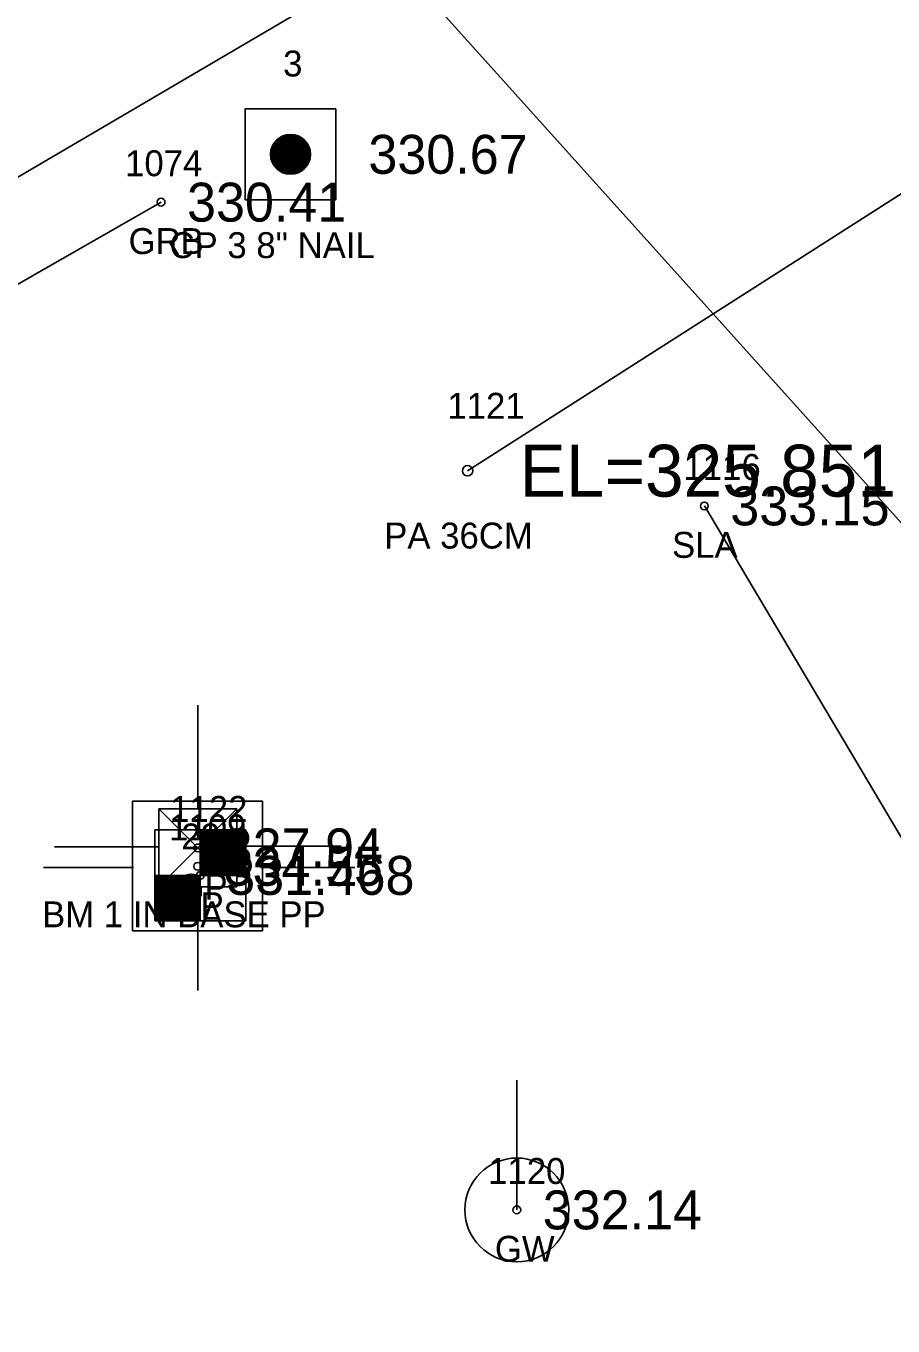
# Model space of a CAD drawing. Extents: x 2231119 to 2232595, y 1035731 to 1037094.
# Drawn here: x 2231678 to 2231711.4, y 1036450.5 to 1036500.6 of the extents above; entities that cross this region are included whole.
import ezdxf

# ---------------------------------------------------------------- set-up
doc = ezdxf.new("R2010")
doc.units = 0
for name, color, linetype in [('RD_EX_DR_Pipe', 7, 'Continuous'), ('RD_EX_DR_Pipe_txCode', 7, 'Continuous'), ('RD_EX_Driveway', 7, 'Continuous'), ('RD_EX_GuardRail', 7, 'Continuous'), ('RD_EX_GuardRail_txCode', 7, 'Continuous'), ('RD_EX_Road', 7, 'Continuous'), ('RD_EX_TX_GuardRail_ELEV', 7, 'Continuous'), ('RD_EX_TX_UT_ELEV', 7, 'Continuous'), ('RD_EX_TX_VEG_ELEV', 7, 'Continuous'), ('RD_EX_UT', 7, 'Continuous'), ('RD_EX_UT_txCode', 7, 'Continuous'), ('RD_EX_VEG', 7, 'Continuous'), ('RD_EX_VEG_txCode', 7, 'Continuous'), ('RD_HC_Survey', 7, 'Continuous'), ('RD_HC_Survey_ELEV', 7, 'Continuous'), ('RD_HC_Survey_txCode', 7, 'Continuous'), ('RD_SMD_Locator', 7, 'Continuous'), ('RD_TX_Pipe_ElevEX', 7, 'Continuous')]:
    doc.layers.add(name, color=color, linetype=linetype)

msp = doc.modelspace()

# ---------------------------------------------------------------- linework, layer by layer
at = {"layer": 'RD_EX_DR_Pipe'}
msp.add_line((2231694.987, 1036483.445), (2231720.193, 1036499.548), dxfattribs=at)
at = {"layer": 'RD_EX_Driveway'}
msp.add_lwpolyline([(2231692.093, 1036503.238), (2231712.625, 1036480.399), (2231730.963, 1036467.852)], dxfattribs=at)
at = {"layer": 'RD_EX_GuardRail'}
msp.add_lwpolyline([(2231470.541, 1036358.212), (2231510.971, 1036390.403), (2231547.273, 1036414.453), (2231612.034, 1036453.053), (2231683.178, 1036493.793)], dxfattribs=at)
at = {"layer": 'RD_EX_Road'}
msp.add_lwpolyline([(2231606.098, 1036462.918), (2231610.57, 1036455.357), (2231692.093, 1036503.238), (2231706.071, 1036512.594), (2231777.095, 1036553.27), (2231861.393, 1036604.653), (2231946.389, 1036654.771), (2232031.075, 1036704.2), (2232117.063, 1036755.157), (2232199.91, 1036803.805), (2232286.695, 1036855.364)], dxfattribs=at)
at = {"layer": 'RD_EX_UT'}
for p, q in [((2231684.591, 1036470.408), (2231684.591, 1036474.408)), ((2231687.079, 1036470.709), (2231682.079, 1036470.709)), ((2231682.079, 1036470.709), (2231682.079, 1036465.709)), ((2231687.079, 1036465.709), (2231687.079, 1036470.709)), ((2231686.091, 1036470.408), (2231683.091, 1036467.408)), ((2231683.091, 1036470.408), (2231686.091, 1036467.408)), ((2231686.091, 1036470.408), (2231683.091, 1036470.408)), ((2231683.091, 1036470.408), (2231683.091, 1036467.408)), ((2231686.091, 1036467.408), (2231686.091, 1036470.408)), ((2231683.067, 1036468.956), (2231679.067, 1036468.956)), ((2231686.105, 1036468.974), (2231690.121, 1036468.974)), ((2231678.648, 1036468.147), (2231682.117, 1036468.147)), ((2231687.008, 1036468.147), (2231690.648, 1036468.147)), ((2231683.091, 1036467.408), (2231686.091, 1036467.408)), ((2231684.591, 1036467.408), (2231684.591, 1036463.408)), ((2231682.079, 1036465.709), (2231687.079, 1036465.709)), ((2231696.881, 1036454.958), (2231696.881, 1036459.958))]:
    msp.add_line(p, q, dxfattribs=at)
msp.add_circle((2231696.881, 1036454.958), 1.999, dxfattribs=at)
at = {"layer": 'RD_EX_VEG'}
msp.add_line((2231704.106, 1036482.087), (2231712.557, 1036467.849), dxfattribs=at)
at = {"layer": 'RD_HC_Survey'}
for p, q in [((2231687.688, 1036495.032), (2231687.688, 1036496.241)), ((2231687.713, 1036495.013), (2231687.713, 1036496.259)), ((2231687.737, 1036494.996), (2231687.737, 1036496.277)), ((2231687.762, 1036494.98), (2231687.762, 1036496.293)), ((2231687.787, 1036494.966), (2231687.787, 1036496.307)), ((2231687.812, 1036494.952), (2231687.812, 1036496.32)), ((2231687.836, 1036494.94), (2231687.836, 1036496.333)), ((2231687.861, 1036494.929), (2231687.861, 1036496.344)), ((2231687.886, 1036494.919), (2231687.886, 1036496.354)), ((2231687.911, 1036494.91), (2231687.911, 1036496.363)), ((2231687.935, 1036494.902), (2231687.935, 1036496.371)), ((2231687.96, 1036494.894), (2231687.96, 1036496.378)), ((2231687.985, 1036494.888), (2231687.985, 1036496.385)), ((2231688.01, 1036494.882), (2231688.01, 1036496.39)), ((2231688.034, 1036494.878), (2231688.034, 1036496.395)), ((2231688.059, 1036494.874), (2231688.059, 1036496.399)), ((2231688.084, 1036494.871), (2231688.084, 1036496.402)), ((2231688.109, 1036494.869), (2231688.109, 1036496.404)), ((2231688.133, 1036494.867), (2231688.133, 1036496.405)), ((2231688.158, 1036494.867), (2231688.158, 1036496.406)), ((2231688.183, 1036494.867), (2231688.183, 1036496.406)), ((2231688.208, 1036494.868), (2231688.208, 1036496.405)), ((2231688.232, 1036494.87), (2231688.232, 1036496.403)), ((2231688.257, 1036494.872), (2231688.257, 1036496.4)), ((2231688.282, 1036494.876), (2231688.282, 1036496.397)), ((2231688.307, 1036494.88), (2231688.307, 1036496.392)), ((2231688.331, 1036494.885), (2231688.331, 1036496.387)), ((2231688.356, 1036494.891), (2231688.356, 1036496.381)), ((2231688.381, 1036494.898), (2231688.381, 1036496.375)), ((2231688.406, 1036494.906), (2231688.406, 1036496.367)), ((2231688.43, 1036494.914), (2231688.43, 1036496.358)), ((2231688.455, 1036494.924), (2231688.455, 1036496.349)), ((2231688.48, 1036494.935), (2231688.48, 1036496.338)), ((2231688.505, 1036494.946), (2231688.505, 1036496.326)), ((2231688.529, 1036494.959), (2231688.529, 1036496.314)), ((2231688.554, 1036494.973), (2231688.554, 1036496.3)), ((2231688.579, 1036494.988), (2231688.579, 1036496.284)), ((2231688.604, 1036495.005), (2231688.604, 1036496.268)), ((2231688.628, 1036495.023), (2231688.628, 1036496.25)), ((2231687.416, 1036495.457), (2231687.416, 1036495.815)), ((2231687.44, 1036495.375), (2231687.44, 1036495.898)), ((2231687.465, 1036495.314), (2231687.465, 1036495.958)), ((2231687.49, 1036495.265), (2231687.49, 1036496.007)), ((2231687.515, 1036495.223), (2231687.515, 1036496.049)), ((2231687.539, 1036495.187), (2231687.539, 1036496.086)), ((2231687.564, 1036495.154), (2231687.564, 1036496.118)), ((2231687.589, 1036495.125), (2231687.589, 1036496.148)), ((2231687.614, 1036495.099), (2231687.614, 1036496.174)), ((2231687.638, 1036495.074), (2231687.638, 1036496.198)), ((2231687.663, 1036495.052), (2231687.663, 1036496.22)), ((2231688.653, 1036495.042), (2231688.653, 1036496.23)), ((2231688.678, 1036495.064), (2231688.678, 1036496.209)), ((2231688.703, 1036495.087), (2231688.703, 1036496.186)), ((2231688.727, 1036495.112), (2231688.727, 1036496.16)), ((2231688.752, 1036495.14), (2231688.752, 1036496.133)), ((2231688.777, 1036495.171), (2231688.777, 1036496.102)), ((2231688.802, 1036495.205), (2231688.802, 1036496.067)), ((2231688.826, 1036495.245), (2231688.826, 1036496.028)), ((2231688.851, 1036495.29), (2231688.851, 1036495.983)), ((2231688.876, 1036495.344), (2231688.876, 1036495.929)), ((2231688.901, 1036495.414), (2231688.901, 1036495.859)), ((2231688.925, 1036495.525), (2231688.925, 1036495.748)), ((2231684.689, 1036469.599), (2231684.689, 1036466.099)), ((2231684.706, 1036469.599), (2231684.706, 1036467.849)), ((2231684.731, 1036469.599), (2231684.731, 1036467.849)), ((2231684.756, 1036469.599), (2231684.756, 1036467.849)), ((2231684.78, 1036469.599), (2231684.78, 1036467.849)), ((2231684.805, 1036469.599), (2231684.805, 1036467.849)), ((2231684.83, 1036469.599), (2231684.83, 1036467.849)), ((2231684.855, 1036469.599), (2231684.855, 1036467.849)), ((2231684.879, 1036469.599), (2231684.879, 1036467.849)), ((2231684.904, 1036469.599), (2231684.904, 1036467.849)), ((2231684.929, 1036469.599), (2231684.929, 1036467.849)), ((2231684.954, 1036469.599), (2231684.954, 1036467.849)), ((2231684.978, 1036469.599), (2231684.978, 1036467.849)), ((2231685.003, 1036469.599), (2231685.003, 1036467.849)), ((2231685.028, 1036469.599), (2231685.028, 1036467.849)), ((2231685.053, 1036469.599), (2231685.053, 1036467.849)), ((2231685.077, 1036469.599), (2231685.077, 1036467.849)), ((2231685.102, 1036469.599), (2231685.102, 1036467.849)), ((2231685.127, 1036469.599), (2231685.127, 1036467.849)), ((2231685.152, 1036469.599), (2231685.152, 1036467.849)), ((2231685.176, 1036469.599), (2231685.176, 1036467.849)), ((2231685.201, 1036469.599), (2231685.201, 1036467.849)), ((2231685.226, 1036469.599), (2231685.226, 1036467.849)), ((2231685.251, 1036469.599), (2231685.251, 1036467.849)), ((2231685.275, 1036469.599), (2231685.275, 1036467.849)), ((2231685.3, 1036469.599), (2231685.3, 1036467.849)), ((2231685.325, 1036469.599), (2231685.325, 1036467.849)), ((2231685.35, 1036469.599), (2231685.35, 1036467.849)), ((2231685.374, 1036469.599), (2231685.374, 1036467.849)), ((2231685.399, 1036469.599), (2231685.399, 1036467.849)), ((2231685.424, 1036469.599), (2231685.424, 1036467.849)), ((2231685.449, 1036469.599), (2231685.449, 1036467.849)), ((2231685.473, 1036469.599), (2231685.473, 1036467.849)), ((2231685.498, 1036469.599), (2231685.498, 1036467.849)), ((2231685.523, 1036469.599), (2231685.523, 1036467.849)), ((2231685.548, 1036469.599), (2231685.548, 1036467.849)), ((2231685.572, 1036469.599), (2231685.572, 1036467.849)), ((2231685.597, 1036469.599), (2231685.597, 1036467.849)), ((2231685.622, 1036469.599), (2231685.622, 1036467.849)), ((2231685.647, 1036469.599), (2231685.647, 1036467.849)), ((2231685.671, 1036469.599), (2231685.671, 1036467.849)), ((2231685.696, 1036469.599), (2231685.696, 1036467.849)), ((2231685.721, 1036469.599), (2231685.721, 1036467.849)), ((2231685.746, 1036469.599), (2231685.746, 1036467.849)), ((2231685.77, 1036469.599), (2231685.77, 1036467.849)), ((2231685.795, 1036469.599), (2231685.795, 1036467.849)), ((2231685.82, 1036469.599), (2231685.82, 1036467.849)), ((2231685.845, 1036469.599), (2231685.845, 1036467.849)), ((2231685.869, 1036469.599), (2231685.869, 1036467.849)), ((2231685.894, 1036469.599), (2231685.894, 1036467.849)), ((2231685.919, 1036469.599), (2231685.919, 1036467.849)), ((2231685.944, 1036469.599), (2231685.944, 1036467.849)), ((2231685.968, 1036469.599), (2231685.968, 1036467.849)), ((2231685.993, 1036469.599), (2231685.993, 1036467.849)), ((2231686.018, 1036469.599), (2231686.018, 1036467.849)), ((2231686.043, 1036469.599), (2231686.043, 1036467.849)), ((2231686.067, 1036469.599), (2231686.067, 1036467.849)), ((2231686.092, 1036469.599), (2231686.092, 1036467.849)), ((2231686.117, 1036469.599), (2231686.117, 1036467.849)), ((2231686.142, 1036469.599), (2231686.142, 1036467.849)), ((2231686.166, 1036469.599), (2231686.166, 1036467.849)), ((2231686.191, 1036469.599), (2231686.191, 1036467.849)), ((2231686.216, 1036469.599), (2231686.216, 1036467.849)), ((2231686.241, 1036469.599), (2231686.241, 1036467.849)), ((2231686.265, 1036469.599), (2231686.265, 1036467.849)), ((2231686.29, 1036469.599), (2231686.29, 1036467.849)), ((2231686.315, 1036469.599), (2231686.315, 1036467.849)), ((2231686.34, 1036469.599), (2231686.34, 1036467.849)), ((2231686.364, 1036469.599), (2231686.364, 1036467.849)), ((2231686.389, 1036469.599), (2231686.389, 1036467.849)), ((2231686.414, 1036469.599), (2231686.414, 1036467.849)), ((2231686.439, 1036467.849), (2231682.939, 1036467.849)), ((2231682.939, 1036467.849), (2231682.939, 1036466.099)), ((2231682.963, 1036467.849), (2231682.963, 1036466.099)), ((2231682.988, 1036467.849), (2231682.988, 1036466.099)), ((2231683.013, 1036467.849), (2231683.013, 1036466.099)), ((2231683.038, 1036467.849), (2231683.038, 1036466.099)), ((2231683.062, 1036467.849), (2231683.062, 1036466.099)), ((2231683.087, 1036467.849), (2231683.087, 1036466.099)), ((2231683.112, 1036467.849), (2231683.112, 1036466.099)), ((2231683.137, 1036467.849), (2231683.137, 1036466.099)), ((2231683.161, 1036467.849), (2231683.161, 1036466.099)), ((2231683.186, 1036467.849), (2231683.186, 1036466.099)), ((2231683.211, 1036467.849), (2231683.211, 1036466.099)), ((2231683.236, 1036467.849), (2231683.236, 1036466.099)), ((2231683.26, 1036467.849), (2231683.26, 1036466.099)), ((2231683.285, 1036467.849), (2231683.285, 1036466.099)), ((2231683.31, 1036467.849), (2231683.31, 1036466.099)), ((2231683.335, 1036467.849), (2231683.335, 1036466.099)), ((2231683.359, 1036467.849), (2231683.359, 1036466.099)), ((2231683.384, 1036467.849), (2231683.384, 1036466.099)), ((2231683.409, 1036467.849), (2231683.409, 1036466.099)), ((2231683.434, 1036467.849), (2231683.434, 1036466.099)), ((2231683.458, 1036467.849), (2231683.458, 1036466.099)), ((2231683.483, 1036467.849), (2231683.483, 1036466.099)), ((2231683.508, 1036467.849), (2231683.508, 1036466.099)), ((2231683.533, 1036467.849), (2231683.533, 1036466.099)), ((2231683.557, 1036467.849), (2231683.557, 1036466.099)), ((2231683.582, 1036467.849), (2231683.582, 1036466.099)), ((2231683.607, 1036467.849), (2231683.607, 1036466.099)), ((2231683.632, 1036467.849), (2231683.632, 1036466.099)), ((2231683.656, 1036467.849), (2231683.656, 1036466.099)), ((2231683.681, 1036467.849), (2231683.681, 1036466.099)), ((2231683.706, 1036467.849), (2231683.706, 1036466.099)), ((2231683.731, 1036467.849), (2231683.731, 1036466.099)), ((2231683.755, 1036467.849), (2231683.755, 1036466.099)), ((2231683.78, 1036467.849), (2231683.78, 1036466.099)), ((2231683.805, 1036467.849), (2231683.805, 1036466.099)), ((2231683.83, 1036467.849), (2231683.83, 1036466.099)), ((2231683.854, 1036467.849), (2231683.854, 1036466.099)), ((2231683.879, 1036467.849), (2231683.879, 1036466.099)), ((2231683.904, 1036467.849), (2231683.904, 1036466.099)), ((2231683.929, 1036467.849), (2231683.929, 1036466.099)), ((2231683.953, 1036467.849), (2231683.953, 1036466.099)), ((2231683.978, 1036467.849), (2231683.978, 1036466.099)), ((2231684.003, 1036467.849), (2231684.003, 1036466.099)), ((2231684.028, 1036467.849), (2231684.028, 1036466.099)), ((2231684.052, 1036467.849), (2231684.052, 1036466.099)), ((2231684.077, 1036467.849), (2231684.077, 1036466.099)), ((2231684.102, 1036467.849), (2231684.102, 1036466.099)), ((2231684.127, 1036467.849), (2231684.127, 1036466.099)), ((2231684.151, 1036467.849), (2231684.151, 1036466.099)), ((2231684.176, 1036467.849), (2231684.176, 1036466.099)), ((2231684.201, 1036467.849), (2231684.201, 1036466.099)), ((2231684.226, 1036467.849), (2231684.226, 1036466.099)), ((2231684.25, 1036467.849), (2231684.25, 1036466.099)), ((2231684.275, 1036467.849), (2231684.275, 1036466.099)), ((2231684.3, 1036467.849), (2231684.3, 1036466.099)), ((2231684.325, 1036467.849), (2231684.325, 1036466.099)), ((2231684.349, 1036467.849), (2231684.349, 1036466.099)), ((2231684.374, 1036467.849), (2231684.374, 1036466.099)), ((2231684.399, 1036467.849), (2231684.399, 1036466.099)), ((2231684.424, 1036467.849), (2231684.424, 1036466.099)), ((2231684.448, 1036467.849), (2231684.448, 1036466.099)), ((2231684.473, 1036467.849), (2231684.473, 1036466.099)), ((2231684.498, 1036467.849), (2231684.498, 1036466.099)), ((2231684.523, 1036467.849), (2231684.523, 1036466.099)), ((2231684.547, 1036467.849), (2231684.547, 1036466.099)), ((2231684.572, 1036467.849), (2231684.572, 1036466.099)), ((2231684.597, 1036467.849), (2231684.597, 1036466.099)), ((2231684.622, 1036467.849), (2231684.622, 1036466.099)), ((2231684.646, 1036467.849), (2231684.646, 1036466.099)), ((2231684.671, 1036467.849), (2231684.671, 1036466.099))]:
    msp.add_line(p, q, dxfattribs=at)
for points in [[(2231689.914, 1036497.386), (2231686.414, 1036497.386), (2231686.414, 1036493.886), (2231689.914, 1036493.886)], [(2231686.439, 1036469.599), (2231682.939, 1036469.599), (2231682.939, 1036466.099), (2231686.439, 1036466.099)]]:
    msp.add_lwpolyline(points, close=True, dxfattribs=at)
msp.add_circle((2231688.164, 1036495.636), 0.769, dxfattribs=at)
at = {"layer": 'RD_SMD_Locator'}
for centre, radius in [((2231688.164, 1036495.636), 0.15), ((2231683.178, 1036493.793), 0.15), ((2231694.987, 1036483.445), 0.2), ((2231704.106, 1036482.087), 0.15), ((2231684.591, 1036468.908), 0.15), ((2231684.588, 1036468.2), 0.15), ((2231684.689, 1036467.849), 0.15), ((2231696.881, 1036454.958), 0.15)]:
    msp.add_circle(centre, radius, dxfattribs=at)

# ---------------------------------------------------------------- texts
at = {"layer": 'RD_EX_DR_Pipe_txCode'}
for s, p in [('1121', (2231694.207, 1036485.445)), ('PA 36CM', (2231691.774, 1036480.445))]:
    msp.add_text(s, height=1, dxfattribs=at).set_placement(p)
at = {"layer": 'RD_EX_GuardRail_txCode'}
for s, p in [('1074', (2231681.792, 1036494.793)), ('GRB', (2231681.926, 1036491.793))]:
    msp.add_text(s, height=1, dxfattribs=at).set_placement(p)
at = {"layer": 'RD_EX_TX_GuardRail_ELEV'}
msp.add_text('330.41', height=1.5, dxfattribs=at).set_placement((2231684.178, 1036493.043))
at = {"layer": 'RD_EX_TX_UT_ELEV'}
for s, p in [('327.94', (2231685.591, 1036468.158)), ('332.14', (2231697.881, 1036454.208))]:
    msp.add_text(s, height=1.5, dxfattribs=at).set_placement(p)
at = {"layer": 'RD_EX_TX_VEG_ELEV'}
msp.add_text('333.15', height=1.5, dxfattribs=at).set_placement((2231705.106, 1036481.337))
at = {"layer": 'RD_EX_UT_txCode'}
for s, p in [('1122', (2231683.528, 1036469.908)), ('1109', (2231683.486, 1036469.2)), ('GP', (2231683.812, 1036466.908)), ('PP', (2231683.809, 1036466.2)), ('1120', (2231695.778, 1036455.958)), ('GW', (2231696.038, 1036452.958))]:
    msp.add_text(s, height=1, dxfattribs=at).set_placement(p)
at = {"layer": 'RD_EX_VEG_txCode'}
for s, p in [('1116', (2231703.303, 1036483.087)), ('SLA', (2231702.862, 1036480.087))]:
    msp.add_text(s, height=1, dxfattribs=at).set_placement(p)
at = {"layer": 'RD_HC_Survey_ELEV'}
for s, p in [('330.67', (2231691.164, 1036494.886)), ('334.55', (2231685.588, 1036467.45)), ('331.468', (2231685.689, 1036467.099))]:
    msp.add_text(s, height=1.5, dxfattribs=at).set_placement(p)
at = {"layer": 'RD_HC_Survey_txCode'}
for s, p in [('3', (2231687.881, 1036498.636)), ('CP 3 8" NAIL', (2231683.503, 1036491.636)), ('22', (2231683.956, 1036468.849)), ('BM 1 IN BASE PP', (2231678.594, 1036465.849))]:
    msp.add_text(s, height=1, dxfattribs=at).set_placement(p)
at = {"layer": 'RD_TX_Pipe_ElevEX'}
msp.add_text('EL=325.851', height=2, dxfattribs=at).set_placement((2231696.987, 1036482.445))

doc.saveas('drawing.dxf')
